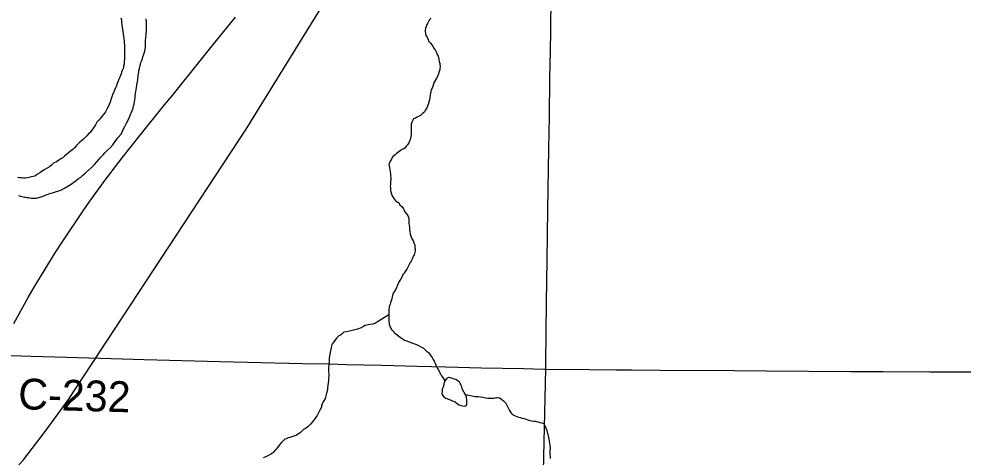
# Model space of a CAD drawing. Extents: x 2.1 to 73.9, y 4 to 26.
# Drawn here: x 43.618 to 44.489, y 21.257 to 21.661 of the extents above; entities that cross this region are included whole.
import ezdxf

# ---------------------------------------------------------------- set-up
doc = ezdxf.new("R2010")
doc.units = 0
for name, color, linetype in [('GM_X_County_Road', 7, 'Continuous'), ('GM_X_County_Road_Text', 7, 'Continuous'), ('GM_X_Major_River', 7, 'Continuous'), ('GM_X_Minor_Lake', 7, 'Continuous'), ('GM_X_Minor_River', 7, 'Continuous'), ('GM_X_Rail_Line', 7, 'Continuous'), ('GM_X_US_Route', 7, 'Continuous')]:
    doc.layers.add(name, color=color, linetype=linetype)

msp = doc.modelspace()

# ---------------------------------------------------------------- linework, layer by layer
at = {"layer": 'GM_X_County_Road'}
for points in [[(44.10393, 21.3377), (44.10403, 21.34329), (44.10477, 21.39925), (44.10542, 21.4381), (44.10597, 21.48473), (44.10688, 21.54067), (44.10737, 21.57021), (44.10789, 21.60595), (44.10825, 21.63082), (44.10862, 21.64946), (44.10908, 21.6821), (44.10984, 21.73028), (44.11043, 21.76913), (44.11092, 21.79089), (44.1112, 21.80643), (44.11141, 21.8344), (44.11162, 21.84839), (44.11188, 21.8553), (44.11201, 21.85939)], [(43.60105, 21.35085), (43.60192, 21.35056), (43.60417, 21.35015), (43.60692, 21.35006), (43.61125, 21.3501), (43.62976, 21.34962), (43.64062, 21.3492), (43.66237, 21.34853), (43.69345, 21.3477), (43.73385, 21.34665), (43.80378, 21.34482), (43.87993, 21.34297), (43.90479, 21.34239), (43.92033, 21.34199), (43.95297, 21.34123), (43.9856, 21.34034), (44.01202, 21.33982), (44.04465, 21.33896), (44.0835, 21.33811), (44.10215, 21.33771), (44.10393, 21.3377)], [(44.09956, 21.1266), (44.09966, 21.13442), (44.10002, 21.16149), (44.10124, 21.21588), (44.10274, 21.28425), (44.10393, 21.3377)], [(44.10393, 21.3377), (44.14413, 21.33738), (44.169, 21.33712), (44.18299, 21.33709), (44.20941, 21.33682), (44.27781, 21.33624), (44.30734, 21.33609), (44.38506, 21.33548), (44.4146, 21.33542), (44.45812, 21.33522), (44.47989, 21.3352), (44.55606, 21.33514), (44.59958, 21.33496), (44.60363, 21.33493)]]:
    msp.add_lwpolyline(points, dxfattribs=at)
at = {"layer": 'GM_X_Major_River'}
for points in [[(43.71254, 21.66166), (43.71288, 21.65975), (43.71302, 21.65766), (43.71334, 21.65499), (43.71366, 21.65251), (43.71417, 21.64946), (43.71466, 21.64603), (43.71516, 21.64279), (43.71577, 21.63613), (43.7159, 21.63366), (43.71584, 21.63081), (43.71578, 21.62834), (43.71573, 21.62606), (43.71567, 21.6234), (43.71562, 21.62093), (43.71538, 21.61904), (43.71496, 21.61696), (43.71473, 21.61545), (43.71432, 21.61413), (43.71373, 21.613), (43.71312, 21.61111), (43.71271, 21.60979), (43.7121, 21.60829), (43.7115, 21.60678), (43.7107, 21.60509), (43.7099, 21.60321), (43.70908, 21.60095), (43.70827, 21.59869), (43.70708, 21.59624), (43.70606, 21.59323), (43.70486, 21.5906), (43.70344, 21.58683), (43.70243, 21.58381), (43.70122, 21.5808), (43.70022, 21.57854), (43.69922, 21.57667), (43.69824, 21.57498), (43.69745, 21.57367), (43.69628, 21.57237), (43.69491, 21.57069), (43.69354, 21.56901), (43.69217, 21.56714), (43.69041, 21.56528), (43.68903, 21.56284), (43.68785, 21.56116), (43.68647, 21.5591), (43.68549, 21.5576), (43.68412, 21.55593), (43.68256, 21.55444), (43.6812, 21.55276), (43.67945, 21.55128), (43.67789, 21.54961), (43.67615, 21.54813), (43.67402, 21.54628), (43.67129, 21.54349), (43.66973, 21.54163), (43.66818, 21.54014), (43.66605, 21.53848), (43.66062, 21.53386), (43.65888, 21.53257), (43.65714, 21.53146), (43.65522, 21.53037), (43.65309, 21.5289), (43.6504, 21.52763), (43.64846, 21.52558), (43.64672, 21.52429), (43.6446, 21.52301), (43.64247, 21.52154), (43.63997, 21.52027), (43.63765, 21.51861), (43.63572, 21.51732), (43.63418, 21.51622), (43.63303, 21.51568), (43.63169, 21.51533), (43.62996, 21.5148), (43.62767, 21.51428), (43.62633, 21.51393)], [(43.6999, 21.53923), (43.70243, 21.54164), (43.70496, 21.54443), (43.70731, 21.54742), (43.70967, 21.55097), (43.7126, 21.55432), (43.7144, 21.55846), (43.71618, 21.56127), (43.71777, 21.56428), (43.71916, 21.56709), (43.72036, 21.56992), (43.72137, 21.57236), (43.72218, 21.57462), (43.72318, 21.57669), (43.72379, 21.57858), (43.72421, 21.58028), (43.72463, 21.58198), (43.72506, 21.58425), (43.72529, 21.58595), (43.72551, 21.58766), (43.72573, 21.58898), (43.72576, 21.58993), (43.72597, 21.59106), (43.726, 21.5922), (43.72621, 21.59315), (43.72687, 21.59731), (43.72729, 21.59901), (43.72753, 21.60129), (43.72776, 21.6028), (43.72798, 21.60432), (43.7282, 21.60564), (43.72842, 21.60696), (43.72845, 21.60829), (43.72867, 21.60981), (43.7289, 21.61132), (43.72913, 21.61303), (43.72955, 21.61492), (43.72978, 21.61662), (43.7304, 21.61889), (43.73081, 21.6204), (43.73161, 21.62209), (43.73223, 21.62397), (43.73264, 21.62568), (43.73364, 21.62793), (43.73469, 21.63209), (43.73513, 21.63493), (43.73517, 21.63645), (43.735, 21.63759), (43.73526, 21.64043), (43.73551, 21.64328), (43.73577, 21.6465), (43.73604, 21.64991), (43.73613, 21.65371), (43.7362, 21.65713), (43.7359, 21.66074)], [(43.61817, 21.49759), (43.61987, 21.49717), (43.62119, 21.49676), (43.62233, 21.49635), (43.62384, 21.49613), (43.62479, 21.49611), (43.62593, 21.49589), (43.62726, 21.49586), (43.62858, 21.49564), (43.62991, 21.49523), (43.63123, 21.4952), (43.63238, 21.49517), (43.63428, 21.49513), (43.6358, 21.49548), (43.64078, 21.49707), (43.6427, 21.49798), (43.64443, 21.4987), (43.64615, 21.49923), (43.64807, 21.49995), (43.65036, 21.50046), (43.65305, 21.50135), (43.65707, 21.50259), (43.66034, 21.50461), (43.66343, 21.50644), (43.66651, 21.50827), (43.66902, 21.51011), (43.67115, 21.51158), (43.67327, 21.51324), (43.6754, 21.51471), (43.67734, 21.51638), (43.67966, 21.51841), (43.68238, 21.52063), (43.68491, 21.52323), (43.68802, 21.52639), (43.69016, 21.52862), (43.69211, 21.53086), (43.69406, 21.53309), (43.69601, 21.53514), (43.69777, 21.53719), (43.6999, 21.53923)], [(43.62633, 21.51393), (43.62423, 21.5136), (43.62309, 21.51362), (43.62215, 21.51383), (43.62063, 21.51387), (43.61892, 21.5141), (43.61703, 21.51433)]]:
    msp.add_lwpolyline(points, dxfattribs=at)
at = {"layer": 'GM_X_Minor_Lake'}
for points in [[(44.01155, 21.3274), (44.01049, 21.32545), (44.00965, 21.32205), (44.00905, 21.32054), (44.00864, 21.31922), (44.00843, 21.31827), (44.0084, 21.31695), (44.00836, 21.31524), (44.0087, 21.31371), (44.01019, 21.31196), (44.01187, 21.31098), (44.01432, 21.30997), (44.01545, 21.30957), (44.0164, 21.30916), (44.0179, 21.30856), (44.01922, 21.30796), (44.02054, 21.30755), (44.02259, 21.3056), (44.02428, 21.30462), (44.0256, 21.30402), (44.0273, 21.30379), (44.02882, 21.30356), (44.03015, 21.30372), (44.03112, 21.30446), (44.03114, 21.30541), (44.03135, 21.30635), (44.03138, 21.30749), (44.0314, 21.30863), (44.0309, 21.31168), (44.03055, 21.31283), (44.03001, 21.31417), (44.02946, 21.31513), (44.02872, 21.3161), (44.02817, 21.31725), (44.02763, 21.31822), (44.02709, 21.31956), (44.02655, 21.32128), (44.0262, 21.32243), (44.02565, 21.32339), (44.0251, 21.32435), (44.02456, 21.3255), (44.02362, 21.32629), (44.02194, 21.32746), (44.021, 21.32805), (44.01968, 21.32846), (44.01798, 21.32888), (44.01609, 21.3295), (44.01477, 21.32991), (44.0145, 21.32981)], [(44.0145, 21.32981), (44.01285, 21.32919), (44.01155, 21.3274)]]:
    msp.add_lwpolyline(points, dxfattribs=at)
at = {"layer": 'GM_X_Minor_River'}
for points in [[(43.99788, 21.66121), (43.99709, 21.6597), (43.99631, 21.65877), (43.99571, 21.65765), (43.99511, 21.65614), (43.99412, 21.65464), (43.99372, 21.65351), (43.9933, 21.652), (43.99288, 21.64992), (43.99318, 21.64631), (43.99353, 21.64535), (43.99464, 21.64361), (43.99536, 21.64208), (43.99626, 21.63978), (43.99794, 21.63822), (43.99904, 21.63667), (43.99997, 21.63551), (44.00069, 21.63398), (44.00161, 21.63263), (44.00234, 21.63128), (44.00326, 21.62955), (44.00398, 21.62782), (44.00489, 21.62628), (44.00506, 21.62533), (44.00558, 21.62323), (44.00592, 21.62132), (44.00626, 21.61941), (44.00642, 21.61808), (44.00658, 21.61656), (44.00653, 21.61466), (44.00632, 21.61352), (44.0059, 21.61201), (44.00528, 21.60975), (44.00409, 21.6073), (44.00309, 21.60524), (44.0021, 21.60374), (44.00131, 21.60224), (44.00051, 21.60036), (43.99989, 21.59828), (43.99908, 21.59621), (43.99849, 21.59527), (43.99807, 21.5932), (43.99763, 21.59055), (43.99718, 21.58771), (43.99655, 21.58506), (43.99552, 21.58148), (43.99451, 21.57865)], [(43.99451, 21.57865), (43.99332, 21.57659), (43.99253, 21.57528), (43.99155, 21.57416), (43.9902, 21.57305), (43.98846, 21.57157), (43.98557, 21.56993), (43.98403, 21.56901), (43.98211, 21.56829), (43.98151, 21.56717), (43.98091, 21.56585), (43.98031, 21.56435), (43.97991, 21.56341), (43.97988, 21.56208), (43.97985, 21.56075), (43.97999, 21.55866), (43.97994, 21.55657), (43.97989, 21.55429), (43.97965, 21.55182), (43.97924, 21.5505), (43.97902, 21.54937), (43.97801, 21.54692), (43.97663, 21.54448), (43.97566, 21.54356), (43.97409, 21.5415), (43.97255, 21.5404), (43.9712, 21.53986), (43.96985, 21.53894), (43.9685, 21.53802), (43.96753, 21.53709), (43.96617, 21.53598), (43.96482, 21.53488), (43.96347, 21.53396), (43.96249, 21.53284), (43.9617, 21.53134), (43.9607, 21.52946), (43.95991, 21.52777), (43.95949, 21.52645), (43.95965, 21.52493), (43.95999, 21.52321), (43.96033, 21.5213), (43.96067, 21.51939), (43.961, 21.51749), (43.96127, 21.51254), (43.96104, 21.51046), (43.96079, 21.50799), (43.96076, 21.50648), (43.96091, 21.50476), (43.96105, 21.50267), (43.9612, 21.50096), (43.96173, 21.49923), (43.96227, 21.4977), (43.963, 21.49636), (43.96392, 21.495), (43.96485, 21.49384), (43.96596, 21.49268), (43.96726, 21.49151), (43.96821, 21.49111), (43.96949, 21.48918), (43.97154, 21.48723), (43.97302, 21.4853), (43.97429, 21.4828), (43.97577, 21.48087), (43.97687, 21.47913), (43.97741, 21.4776), (43.97776, 21.47626), (43.97771, 21.47417), (43.97786, 21.47227), (43.9782, 21.47036), (43.97834, 21.46827), (43.97848, 21.46618), (43.97863, 21.46446), (43.97915, 21.46217), (43.97967, 21.46007), (43.9804, 21.45853), (43.98094, 21.45738), (43.98167, 21.45585), (43.98239, 21.45412), (43.98294, 21.45297), (43.98329, 21.45182), (43.98344, 21.45011), (43.98359, 21.44801), (43.98356, 21.44669), (43.98334, 21.44555), (43.98293, 21.44423), (43.98272, 21.4431), (43.98212, 21.44197), (43.98152, 21.44084), (43.98091, 21.43896), (43.97992, 21.43727), (43.97894, 21.43596), (43.97715, 21.4322), (43.97595, 21.42976), (43.97438, 21.42752), (43.9734, 21.42621), (43.97242, 21.4249), (43.97162, 21.42302), (43.97043, 21.42096), (43.96885, 21.41834), (43.96744, 21.41495), (43.96584, 21.41138)], [(43.96584, 21.41138), (43.96426, 21.40875), (43.96348, 21.40763), (43.96308, 21.40669), (43.96246, 21.40443), (43.96203, 21.40254), (43.96161, 21.40065), (43.961, 21.39895), (43.96058, 21.39725), (43.95998, 21.39593), (43.95977, 21.39499), (43.95956, 21.39404), (43.95953, 21.3929), (43.95932, 21.39177), (43.95929, 21.39044), (43.95924, 21.38835), (43.95941, 21.38721), (43.95938, 21.38607), (43.95936, 21.38512), (43.95952, 21.38398), (43.95949, 21.38265), (43.95947, 21.3817), (43.95962, 21.37999), (43.95979, 21.37903), (43.96032, 21.37731), (43.96105, 21.37558), (43.96178, 21.37424), (43.96345, 21.37249), (43.96438, 21.37152), (43.96587, 21.37016), (43.96848, 21.36801), (43.9711, 21.36605), (43.97391, 21.36446), (43.97599, 21.36366), (43.9773, 21.36305), (43.98145, 21.36144), (43.98315, 21.36083), (43.98504, 21.36022), (43.98729, 21.35922), (43.98955, 21.35803), (43.99143, 21.35703), (43.99254, 21.35587), (43.99422, 21.35431), (43.9959, 21.35294), (43.99701, 21.35159), (43.99811, 21.35004), (43.99922, 21.34831), (44.00032, 21.34657), (44.00104, 21.34504), (44.00177, 21.34369), (44.00231, 21.34235), (44.00303, 21.34062), (44.00358, 21.33947), (44.00431, 21.33812), (44.00486, 21.33716), (44.00541, 21.3362), (44.00595, 21.33505), (44.0065, 21.33389), (44.00723, 21.33255), (44.00796, 21.33139), (44.00907, 21.33004), (44.01109, 21.32676)], [(43.95935, 21.38759), (43.94901, 21.38118), (43.94708, 21.37989), (43.94459, 21.37919), (43.94173, 21.37887), (43.93771, 21.37783), (43.93617, 21.37691), (43.93386, 21.37564), (43.93042, 21.37457), (43.92678, 21.37371), (43.92315, 21.37265), (43.92028, 21.37196), (43.9178, 21.37163), (43.91644, 21.37015), (43.91489, 21.36885), (43.91317, 21.36832), (43.91219, 21.3672), (43.91121, 21.36609), (43.90965, 21.36403), (43.90828, 21.36254), (43.90749, 21.36123), (43.90689, 21.35992), (43.90627, 21.35765), (43.90563, 21.35463), (43.90499, 21.35141), (43.90454, 21.34819), (43.90428, 21.34497), (43.90422, 21.34231), (43.90394, 21.33852), (43.90387, 21.33548), (43.90401, 21.33301), (43.90397, 21.3313), (43.90374, 21.3294), (43.90369, 21.32713), (43.90344, 21.32466), (43.9032, 21.32258), (43.90297, 21.32068), (43.90273, 21.31841), (43.9019, 21.31558), (43.90084, 21.31066), (43.89887, 21.30748), (43.89806, 21.30541), (43.89747, 21.30428), (43.89724, 21.30258), (43.89624, 21.30032), (43.89346, 21.29488), (43.89188, 21.29263), (43.88934, 21.28946), (43.88719, 21.28685), (43.88485, 21.28444), (43.88254, 21.28278), (43.88081, 21.28187), (43.87945, 21.28076), (43.8779, 21.27928), (43.87635, 21.27798), (43.87519, 21.27744), (43.87365, 21.27633), (43.87173, 21.27581), (43.87001, 21.27528), (43.86829, 21.27475), (43.86657, 21.27441), (43.86484, 21.2735), (43.8635, 21.27296), (43.86156, 21.27129), (43.8598, 21.26943), (43.85824, 21.26757), (43.85667, 21.26551), (43.85511, 21.26346), (43.85433, 21.26253), (43.85297, 21.26123), (43.85218, 21.2603), (43.85064, 21.25919), (43.84852, 21.25791), (43.84602, 21.25683), (43.84353, 21.25594)], [(44.02995, 21.31428), (44.03606, 21.31289), (44.03871, 21.31245), (44.04023, 21.31242), (44.04118, 21.3124), (44.04213, 21.31238), (44.04346, 21.31216), (44.04592, 21.31172), (44.04838, 21.31128), (44.05065, 21.31085), (44.05312, 21.3108), (44.05483, 21.31076), (44.05636, 21.31091), (44.0575, 21.31108), (44.05884, 21.31143), (44.05998, 21.3114), (44.0615, 21.31118), (44.06281, 21.31039), (44.06393, 21.30941), (44.06505, 21.30843), (44.06616, 21.30727), (44.06728, 21.30611), (44.06819, 21.30437), (44.07074, 21.29957), (44.07166, 21.29803), (44.07258, 21.29687), (44.07351, 21.29589), (44.07463, 21.29511), (44.07595, 21.29451), (44.07727, 21.29391), (44.07878, 21.29331), (44.08048, 21.29289), (44.08218, 21.29247), (44.08407, 21.29205), (44.08577, 21.29163), (44.08747, 21.29102), (44.08936, 21.29041), (44.09106, 21.28999), (44.09295, 21.28975), (44.09428, 21.28953), (44.09523, 21.28932), (44.09712, 21.2889), (44.09863, 21.28848), (44.09996, 21.28827), (44.10128, 21.28786), (44.10222, 21.28764), (44.10274, 21.28554), (44.10366, 21.284), (44.10421, 21.28304), (44.10476, 21.28208), (44.10511, 21.28093), (44.10546, 21.2794), (44.10599, 21.27768), (44.10633, 21.27596), (44.10685, 21.27367), (44.10718, 21.2712), (44.10751, 21.26929), (44.10785, 21.26757), (44.10798, 21.26472), (44.10792, 21.26187), (44.10786, 21.25921), (44.108, 21.25693), (44.10815, 21.25522)]]:
    msp.add_lwpolyline(points, dxfattribs=at)
at = {"layer": 'GM_X_Rail_Line'}
msp.add_lwpolyline([(42.88241, 20.69347), (42.89307, 20.7248), (42.90465, 20.75368), (42.91466, 20.77475), (42.92428, 20.79001), (42.94019, 20.80877), (42.96022, 20.8239), (42.99387, 20.84535), (43.35311, 21.07085), (43.54662, 21.18986), (43.57719, 21.21018), (43.60224, 21.23087), (43.62273, 21.25406), (43.64373, 21.28134), (43.66406, 21.30971), (43.73536, 21.41812), (43.82792, 21.55878), (43.90244, 21.68007), (43.94967, 21.74716), (43.97734, 21.7904), (44.01624, 21.85997)], dxfattribs=at)
at = {"layer": 'GM_X_US_Route'}
msp.add_lwpolyline([(43.61377, 21.37965), (43.6271, 21.40353), (43.63262, 21.41329), (43.63933, 21.42414), (43.65199, 21.44477), (43.65959, 21.45652), (43.67768, 21.48369), (43.68392, 21.49262), (43.69872, 21.5129), (43.70404, 21.51999), (43.70433, 21.52037), (43.71371, 21.53258), (43.73013, 21.55335), (43.75259, 21.58116), (43.75957, 21.5895), (43.76931, 21.60159), (43.77799, 21.61256), (43.79652, 21.63555), (43.81802, 21.66213)], dxfattribs=at)

# ---------------------------------------------------------------- texts
at = {"layer": 'GM_X_County_Road_Text'}
msp.add_text('C-232', height=0.028409, rotation=358.34799, dxfattribs=at).set_placement((43.61755, 21.30076))

doc.saveas('drawing.dxf')
